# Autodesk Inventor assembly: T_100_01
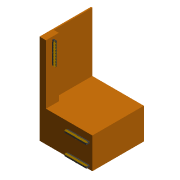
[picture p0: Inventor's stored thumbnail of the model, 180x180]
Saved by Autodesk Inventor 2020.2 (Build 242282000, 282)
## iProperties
Created: 2014-09
Part Number: T_100_01
Document SubType Name: Assembly
Designer: F.Stasiak
Catalog Web Link: www.expertbooks.pl
Manager: www.cadconsulting.pl
Company: Fabian Stasiak CAD Consulting
Author: F.Stasiak
Subject: Zbiór ćwiczeń. Autodesk Inventor 2020. Kurs Professional
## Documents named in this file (3)
- C:\2020_Kurs_Professional\R2 Wiązki\T_100_01.iam
- C:\2020_Kurs_Professional\R2 Wiązki\Komponenty\Konstrukcja_W1.ipt
- C:\2020_Kurs_Professional\Zasoby\ContentCenter\pl-PL\Ribbon Cable Connector\Ribbon Cable Connector-13.ipt
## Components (4 placed, 2 different names)
1. Konstrukcja_W1:1 — Zestawiający:3, Równoległy:5, Równoległy:6, Zestawiający:4, Zestawiający:5, Równoległy:8, Równoległy:9, Równoległy:10
2. Złącze kabla taśmowego Ribbon Cable Connector-13:1 — Zestawiający:5, Równoległy:7, Równoległy:10
3. Złącze kabla taśmowego Ribbon Cable Connector-13:2 — Zestawiający:4, Równoległy:7, Równoległy:8, Równoległy:9
4. Złącze kabla taśmowego Ribbon Cable Connector-13:3 — Zestawiający:3, Równoległy:5, Równoległy:6
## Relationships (9: Flush 6, Mate 3)
- Zestawiający:3 [Mate]: Konstrukcja_W1:1 ↔ Złącze kabla taśmowego Ribbon Cable Connector-13:3
- Równoległy:5 [Flush]: Konstrukcja_W1:1 ↔ Złącze kabla taśmowego Ribbon Cable Connector-13:3
- Równoległy:6 [Flush]: Konstrukcja_W1:1 ↔ Złącze kabla taśmowego Ribbon Cable Connector-13:3
- Zestawiający:4 [Mate]: Konstrukcja_W1:1 ↔ Złącze kabla taśmowego Ribbon Cable Connector-13:2
- Zestawiający:5 [Mate]: Konstrukcja_W1:1 ↔ Złącze kabla taśmowego Ribbon Cable Connector-13:1
- Równoległy:7 [Flush]: Złącze kabla taśmowego Ribbon Cable Connector-13:1 ↔ Złącze kabla taśmowego Ribbon Cable Connector-13:2
- Równoległy:8 [Flush]: Konstrukcja_W1:1 ↔ Złącze kabla taśmowego Ribbon Cable Connector-13:2
- Równoległy:9 [Flush]: Konstrukcja_W1:1 ↔ Złącze kabla taśmowego Ribbon Cable Connector-13:2
- Równoległy:10 [Flush]: Konstrukcja_W1:1 ↔ Złącze kabla taśmowego Ribbon Cable Connector-13:1
